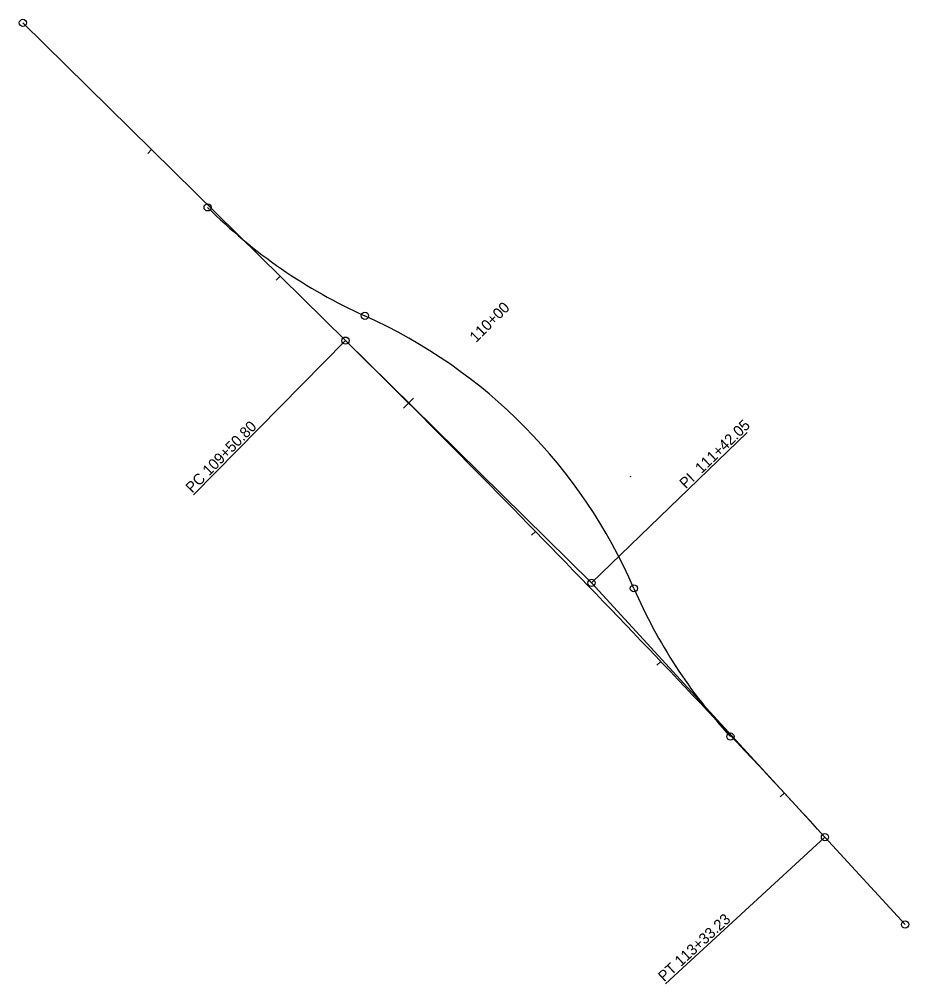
# Model space of a CAD drawing. Extents: x 1655845 to 1665184, y 664876 to 670894.
# Drawn here: x 1661028 to 1661520, y 669964 to 670498 of the extents above; entities that cross this region are included whole.
import ezdxf

# ---------------------------------------------------------------- set-up
doc = ezdxf.new("R2010")
doc.units = 0
for name, color, linetype in [('R_Horz Alg', 7, 'Continuous'), ('R_Horz Alg Annot', 7, 'Continuous'), ('R_Proposed Const Limits_Cut', 7, 'Continuous')]:
    doc.layers.add(name, color=color, linetype=linetype)

msp = doc.modelspace()

# ---------------------------------------------------------------- linework, layer by layer
at = {"layer": 'R_Horz Alg'}
for p, q in [((1661029.53, 670496.2), (1661208.2, 670320.2)), ((1661473.81, 670045.11), (1661518.2, 669996.77))]:
    msp.add_line(p, q, dxfattribs=at)
for centre, radius, start, end in [((1661339.53, 670601.86), 293.82, 225.0245, 245.7806), ((1661098.46, 670065.94), 293.82, 23.4717, 65.7806), ((1655846.99, 664877.91), 7639.44, 42.561815, 45.430038), ((1661637.47, 670300), 293.82, 203.4717, 222.6711)]:
    msp.add_arc(centre, radius, start, end, dxfattribs=at)
at = {"layer": 'R_Horz Alg Annot'}
for p, q in [((1661208.2, 670320.2), (1661344.44, 670185.98)), ((1661344.44, 670185.98), (1661473.81, 670045.11))]:
    msp.add_line(p, q, dxfattribs=at)
for points in [[(1661098.66, 670423.89), (1661100.77, 670426.03)], [(1661169.9, 670353.71), (1661172.01, 670355.85)], [(1661208.2, 670320.2), (1661123.98, 670234.71)], [(1661245.96, 670288.39), (1661240.31, 670282.73)], [(1661344.44, 670185.98), (1661430.77, 670269.33)], [(1661311.31, 670212.37), (1661313.46, 670214.46)], [(1661380.67, 670140.38), (1661382.84, 670142.45)], [(1661449.08, 670067.5), (1661451.28, 670069.54)], [(1661473.81, 670045.11), (1661385.42, 669963.95)]]:
    msp.add_lwpolyline(points, dxfattribs=at)
for centre in [(1661029.53, 670496.2), (1661131.85, 670394.01), (1661218.99, 670333.9), (1661208.2, 670320.2), (1661344.44, 670185.98), (1661367.97, 670182.97), (1661421.44, 670100.85), (1661473.81, 670045.11), (1661518.2, 669996.77)]:
    msp.add_circle(centre, 2, dxfattribs=at)
at = {"layer": 'R_Proposed Const Limits_Cut'}
msp.add_lwpolyline([(1661365.87, 670244.93), (1661366.48, 670245.1)], dxfattribs=at)

# ---------------------------------------------------------------- texts
at = {"layer": 'R_Horz Alg Annot'}
for s, rotation, p in [('110+00', 45.061, (1661280.58, 670318.83)), ('PC 109+50.80', 45.43, (1661123.27, 670235.41)), ('PI  111+42.05', 43.9959, (1661396.7, 670237.83)), ('PT 113+33.23', 42.5618, (1661384.74, 669964.68))]:
    msp.add_text(s, height=6, rotation=rotation, dxfattribs=at).set_placement(p)

doc.saveas('drawing.dxf')
